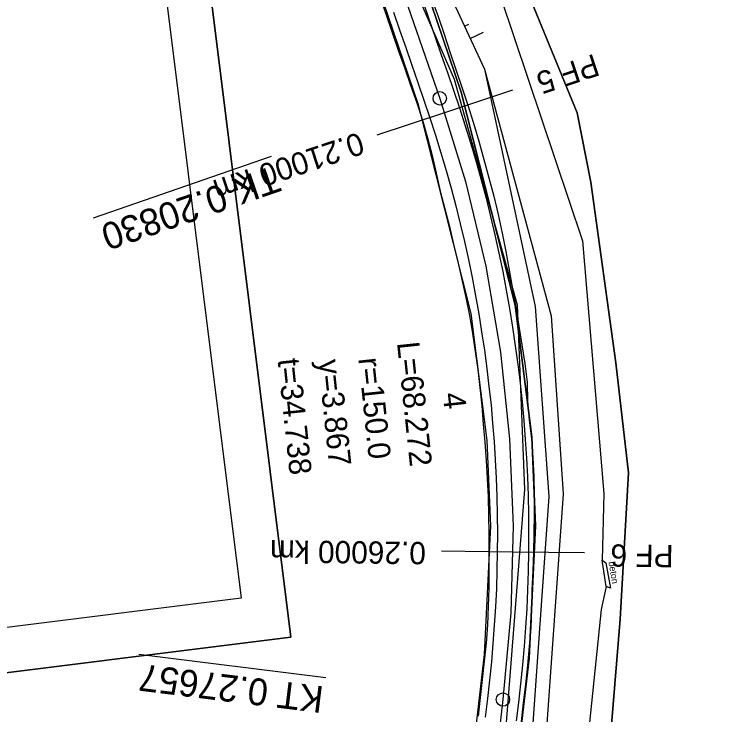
# Model space of a CAD drawing. Extents: x -555887 to -552101, y -1100251 to -1096546.
# Drawn here: x -553961.2 to -553879.9, y -1097845.2 to -1097766.8 of the extents above; entities that cross this region are included whole.
import ezdxf

# ---------------------------------------------------------------- set-up
doc = ezdxf.new("R2010")
doc.units = 0
for name, color, linetype in [('PARCELY_cesty', 7, 'Continuous'), ('PARCELY_VHO', 7, 'Continuous'), ('POLYGONY_SITUACE_PF', 7, 'Continuous'), ('POLYGONY_SITUACE_PF_POPISY', 7, 'Continuous'), ('POLYGONY_SITUACE_PO', 7, 'Continuous'), ('ROZHLED_ram_legenda_1', 7, 'Continuous'), ('ZSST', 7, 'Continuous'), ('zájem', 7, 'Continuous')]:
    doc.layers.add(name, color=color, linetype=linetype)

msp = doc.modelspace()

# ---------------------------------------------------------------- linework, layer by layer
for p, q in [((-553932.416, -1097782.755), (-553952.354, -1097789.637)), ((-553926.28, -1097841.093), (-553947.213, -1097838.51))]:
    msp.add_line(p, q)
at = {"layer": 'PARCELY_cesty'}
for points in [[(-553910.622, -1097956.19), (-553913.42, -1097924.46), (-553903.498, -1097838.889), (-553902.803, -1097824.091), (-553903.199, -1097814.131), (-553905.076, -1097799.369), (-553911.111, -1097775.519), (-553924.494, -1097736.179), (-553926.037, -1097728.701), (-553926.88, -1097721.034), (-553927.942, -1097698.335), (-553927.014, -1097685.697), (-553927.851, -1097681.722), (-553929.538, -1097678.1), (-553932.003, -1097674.954), (-553935.116, -1097672.449), (-553938.716, -1097670.715), (-553942.616, -1097669.842), (-553946.468, -1097669.874), (-554027.52, -1097678.879), (-554030.91, -1097678.33)], [(-553915.615, -1097956.495), (-553918.446, -1097924.391), (-553908.484, -1097838.483), (-553907.808, -1097824.073), (-553908.187, -1097814.546), (-553909.998, -1097800.301), (-553915.909, -1097776.94), (-553929.328, -1097737.494), (-553930.981, -1097729.481), (-553931.867, -1097721.425), (-553932.951, -1097698.268), (-553932.053, -1097686.035), (-553932.625, -1097683.313), (-553933.828, -1097680.732), (-553935.584, -1097678.49), (-553937.803, -1097676.705), (-553940.369, -1097675.469), (-553943.148, -1097674.846), (-553946.14, -1097674.871), (-554026.66, -1097685.902), (-554029.64, -1097687.62)]]:
    msp.add_lwpolyline(points, dxfattribs=at)
at = {"layer": 'PARCELY_VHO'}
for points in [[(-553895.01, -1097951.32), (-553903.94, -1097924.64), (-553898.75, -1097900.98), (-553893.31, -1097834.53), (-553892.36, -1097818.14), (-553893.78, -1097805.84), (-553896.6, -1097785.6), (-553898.1, -1097777.85), (-553916.6, -1097732.86), (-553916.42, -1097704.51), (-553918.4, -1097676.29), (-553917.8, -1097670.8), (-553913.5, -1097649.75), (-553920.52, -1097625.16)], [(-553927.41, -1097628.08), (-553920.29, -1097651.1), (-553924.15, -1097670.8), (-553927.014, -1097685.697), (-553927.942, -1097698.335), (-553926.88, -1097721.034), (-553926.037, -1097728.701), (-553924.494, -1097736.179), (-553911.111, -1097775.519), (-553905.076, -1097799.369), (-553903.199, -1097814.131), (-553902.803, -1097824.091), (-553903.498, -1097838.889), (-553913.42, -1097924.2), (-553904.91, -1097952.6), (-553904.09, -1097966.52), (-553910.368, -1097974.94), (-553913.828, -1098111.034), (-553912.715, -1098125.988), (-553910.789, -1098134.707), (-553870.98, -1098223.96)]]:
    msp.add_lwpolyline(points, dxfattribs=at)
at = {"layer": 'POLYGONY_SITUACE_PF'}
for p, q in [((-553905.372, -1097775.319), (-553912.964, -1097777.843)), ((-553912.964, -1097777.843), (-553920.555, -1097780.367)), ((-553905.313, -1097827.02), (-553913.312, -1097826.921)), ((-553897.313, -1097827.119), (-553905.313, -1097827.02))]:
    msp.add_line(p, q, dxfattribs=at)
at = {"layer": 'POLYGONY_SITUACE_PO'}
for p, q in [((-553925.367, -1097741.88), (-553913.51, -1097776.23)), ((-553920.205, -1097764.915), (-553919.528, -1097766.885)), ((-553915.379, -1097765.453), (-553914.699, -1097767.422)), ((-553915.379, -1097765.453), (-553914.699, -1097767.422)), ((-553914.388, -1097765.111), (-553913.694, -1097767.075)), ((-553918.687, -1097766.595), (-553918.008, -1097768.564)), ((-553918.687, -1097766.595), (-553918.008, -1097768.564)), ((-553919.528, -1097766.885), (-553918.851, -1097768.855)), ((-553914.699, -1097767.422), (-553914.019, -1097769.391)), ((-553914.699, -1097767.422), (-553914.019, -1097769.391)), ((-553913.694, -1097767.075), (-553913.036, -1097769.052)), ((-553918.851, -1097768.855), (-553918.181, -1097770.828)), ((-553918.008, -1097768.564), (-553917.328, -1097770.533)), ((-553918.008, -1097768.564), (-553917.328, -1097770.533)), ((-553913.036, -1097769.052), (-553912.373, -1097771.027)), ((-553914.019, -1097769.391), (-553913.34, -1097771.361)), ((-553914.019, -1097769.391), (-553913.34, -1097771.361)), ((-553917.328, -1097770.533), (-553916.648, -1097772.503)), ((-553917.328, -1097770.533), (-553916.648, -1097772.503)), ((-553918.181, -1097770.828), (-553917.479, -1097772.79)), ((-553913.34, -1097771.361), (-553912.66, -1097773.33)), ((-553913.34, -1097771.361), (-553912.66, -1097773.33)), ((-553912.373, -1097771.027), (-553911.708, -1097773.001)), ((-553917.479, -1097772.79), (-553916.79, -1097774.755)), ((-553916.648, -1097772.503), (-553915.968, -1097774.472)), ((-553916.648, -1097772.503), (-553915.968, -1097774.472)), ((-553911.708, -1097773.001), (-553911.042, -1097774.976)), ((-553912.66, -1097773.33), (-553911.98, -1097775.299)), ((-553912.66, -1097773.33), (-553911.98, -1097775.299)), ((-553916.79, -1097774.755), (-553916.081, -1097776.715)), ((-553915.968, -1097774.472), (-553915.289, -1097776.441)), ((-553915.968, -1097774.472), (-553915.289, -1097776.441)), ((-553911.98, -1097775.299), (-553911.303, -1097777.291)), ((-553911.98, -1097775.299), (-553911.303, -1097777.291)), ((-553911.042, -1097774.976), (-553910.376, -1097776.982)), ((-553913.51, -1097776.23), (-553910.63, -1097785.546)), ((-553916.081, -1097776.715), (-553915.465, -1097778.674)), ((-553915.289, -1097776.441), (-553914.624, -1097778.395)), ((-553915.289, -1097776.441), (-553914.624, -1097778.395)), ((-553910.376, -1097776.982), (-553909.743, -1097779.007)), ((-553911.303, -1097777.291), (-553910.658, -1097779.297)), ((-553911.303, -1097777.291), (-553910.658, -1097779.297)), ((-553915.465, -1097778.674), (-553914.896, -1097780.641)), ((-553914.624, -1097778.395), (-553913.994, -1097780.355)), ((-553914.624, -1097778.395), (-553913.994, -1097780.355)), ((-553910.658, -1097779.297), (-553910.031, -1097781.309)), ((-553910.658, -1097779.297), (-553910.031, -1097781.309)), ((-553909.743, -1097779.007), (-553909.143, -1097781.041)), ((-553913.994, -1097780.355), (-553913.382, -1097782.321)), ((-553913.994, -1097780.355), (-553913.382, -1097782.321)), ((-553914.896, -1097780.641), (-553914.365, -1097782.618)), ((-553909.143, -1097781.041), (-553908.573, -1097783.083)), ((-553910.031, -1097781.309), (-553909.433, -1097783.33)), ((-553910.031, -1097781.309), (-553909.433, -1097783.33)), ((-553914.365, -1097782.618), (-553913.903, -1097784.612)), ((-553913.382, -1097782.321), (-553912.798, -1097784.295)), ((-553913.382, -1097782.321), (-553912.798, -1097784.295)), ((-553909.433, -1097783.33), (-553908.873, -1097785.362)), ((-553909.433, -1097783.33), (-553908.873, -1097785.362)), ((-553908.573, -1097783.083), (-553908.029, -1097785.132)), ((-553912.798, -1097784.295), (-553912.251, -1097786.28)), ((-553912.798, -1097784.295), (-553912.251, -1097786.28)), ((-553913.903, -1097784.612), (-553913.454, -1097786.607)), ((-553908.029, -1097785.132), (-553907.456, -1097787.174)), ((-553910.63, -1097785.546), (-553908.361, -1097795.03)), ((-553908.873, -1097785.362), (-553908.331, -1097787.399)), ((-553908.873, -1097785.362), (-553908.331, -1097787.399)), ((-553913.454, -1097786.607), (-553912.947, -1097788.585)), ((-553912.251, -1097786.28), (-553911.721, -1097788.27)), ((-553912.251, -1097786.28), (-553911.721, -1097788.27)), ((-553908.331, -1097787.399), (-553907.821, -1097789.444)), ((-553908.331, -1097787.399), (-553907.821, -1097789.444)), ((-553907.456, -1097787.174), (-553906.956, -1097789.234)), ((-553912.947, -1097788.585), (-553912.44, -1097790.563)), ((-553911.721, -1097788.27), (-553911.222, -1097790.268)), ((-553911.721, -1097788.27), (-553911.222, -1097790.268)), ((-553906.956, -1097789.234), (-553906.515, -1097791.308)), ((-553907.821, -1097789.444), (-553907.339, -1097791.495)), ((-553907.821, -1097789.444), (-553907.339, -1097791.495)), ((-553912.44, -1097790.563), (-553911.96, -1097792.547)), ((-553911.222, -1097790.268), (-553910.752, -1097792.272)), ((-553911.222, -1097790.268), (-553910.752, -1097792.272)), ((-553907.339, -1097791.495), (-553906.878, -1097793.552)), ((-553907.339, -1097791.495), (-553906.878, -1097793.552)), ((-553906.515, -1097791.308), (-553906.097, -1097793.385)), ((-553911.96, -1097792.547), (-553911.486, -1097794.533)), ((-553910.752, -1097792.272), (-553910.301, -1097794.281)), ((-553910.752, -1097792.272), (-553910.301, -1097794.281)), ((-553906.097, -1097793.385), (-553905.726, -1097795.472)), ((-553910.301, -1097794.281), (-553909.897, -1097796.3)), ((-553910.301, -1097794.281), (-553909.897, -1097796.3)), ((-553906.878, -1097793.552), (-553906.464, -1097795.618)), ((-553906.878, -1097793.552), (-553906.464, -1097795.618)), ((-553911.486, -1097794.533), (-553911.038, -1097796.527)), ((-553908.361, -1097795.03), (-553906.713, -1097804.641)), ((-553906.464, -1097795.618), (-553906.067, -1097797.688)), ((-553906.464, -1097795.618), (-553906.067, -1097797.688)), ((-553905.726, -1097795.472), (-553905.347, -1097797.556)), ((-553911.038, -1097796.527), (-553910.596, -1097798.522)), ((-553909.897, -1097796.3), (-553909.509, -1097798.322)), ((-553909.897, -1097796.3), (-553909.509, -1097798.322)), ((-553909.509, -1097798.322), (-553909.144, -1097800.349)), ((-553909.509, -1097798.322), (-553909.144, -1097800.349)), ((-553906.067, -1097797.688), (-553905.694, -1097799.763)), ((-553906.067, -1097797.688), (-553905.694, -1097799.763)), ((-553905.347, -1097797.556), (-553904.989, -1097799.643)), ((-553910.596, -1097798.522), (-553910.191, -1097800.526)), ((-553905.694, -1097799.763), (-553905.36, -1097801.844)), ((-553905.694, -1097799.763), (-553905.36, -1097801.844)), ((-553904.989, -1097799.643), (-553904.64, -1097801.732)), ((-553910.191, -1097800.526), (-553909.844, -1097802.541)), ((-553909.144, -1097800.349), (-553908.818, -1097802.382)), ((-553909.144, -1097800.349), (-553908.818, -1097802.382)), ((-553908.818, -1097802.382), (-553908.511, -1097804.418)), ((-553908.818, -1097802.382), (-553908.511, -1097804.418)), ((-553905.36, -1097801.844), (-553905.046, -1097803.928)), ((-553905.36, -1097801.844), (-553905.046, -1097803.928)), ((-553904.64, -1097801.732), (-553904.306, -1097803.823)), ((-553909.844, -1097802.541), (-553909.542, -1097804.563)), ((-553905.046, -1097803.928), (-553904.771, -1097806.017)), ((-553905.046, -1097803.928), (-553904.771, -1097806.017)), ((-553904.306, -1097803.823), (-553903.973, -1097805.916)), ((-553909.542, -1097804.563), (-553909.254, -1097806.588)), ((-553908.511, -1097804.418), (-553908.243, -1097806.459)), ((-553908.511, -1097804.418), (-553908.243, -1097806.459)), ((-553906.713, -1097804.641), (-553905.693, -1097814.339)), ((-553908.243, -1097806.459), (-553907.998, -1097808.503)), ((-553908.243, -1097806.459), (-553907.998, -1097808.503)), ((-553904.771, -1097806.017), (-553904.521, -1097808.11)), ((-553904.771, -1097806.017), (-553904.521, -1097808.11)), ((-553903.973, -1097805.916), (-553903.716, -1097808.019)), ((-553909.254, -1097806.588), (-553909.03, -1097808.62)), ((-553903.716, -1097808.019), (-553903.679, -1097810.144)), ((-553909.03, -1097808.62), (-553908.807, -1097810.652)), ((-553907.998, -1097808.503), (-553907.77, -1097810.55)), ((-553907.998, -1097808.503), (-553907.77, -1097810.55)), ((-553904.521, -1097808.11), (-553904.287, -1097810.204)), ((-553904.521, -1097808.11), (-553904.287, -1097810.204)), ((-553904.287, -1097810.204), (-553904.102, -1097812.304)), ((-553904.287, -1097810.204), (-553904.102, -1097812.304)), ((-553903.679, -1097810.144), (-553903.495, -1097812.252)), ((-553908.807, -1097810.652), (-553908.651, -1097812.691)), ((-553907.77, -1097810.55), (-553907.589, -1097812.601)), ((-553907.77, -1097810.55), (-553907.589, -1097812.601)), ((-553908.651, -1097812.691), (-553908.474, -1097814.728)), ((-553907.589, -1097812.601), (-553907.429, -1097814.653)), ((-553907.589, -1097812.601), (-553907.429, -1097814.653)), ((-553904.102, -1097812.304), (-553903.937, -1097814.405)), ((-553904.102, -1097812.304), (-553903.937, -1097814.405)), ((-553903.495, -1097812.252), (-553903.229, -1097814.355)), ((-553905.693, -1097814.339), (-553905.305, -1097824.082)), ((-553903.937, -1097814.405), (-553903.802, -1097816.508)), ((-553903.937, -1097814.405), (-553903.802, -1097816.508)), ((-553903.229, -1097814.355), (-553903.094, -1097816.468)), ((-553908.474, -1097814.728), (-553908.317, -1097816.767)), ((-553907.429, -1097814.653), (-553907.297, -1097816.708)), ((-553907.429, -1097814.653), (-553907.297, -1097816.708)), ((-553908.317, -1097816.767), (-553908.199, -1097818.808)), ((-553907.297, -1097816.708), (-553907.197, -1097818.765)), ((-553907.297, -1097816.708), (-553907.197, -1097818.765)), ((-553903.802, -1097816.508), (-553903.7, -1097818.613)), ((-553903.802, -1097816.508), (-553903.7, -1097818.613)), ((-553903.094, -1097816.468), (-553902.982, -1097818.582)), ((-553903.7, -1097818.613), (-553903.616, -1097820.719)), ((-553903.7, -1097818.613), (-553903.616, -1097820.719)), ((-553902.982, -1097818.582), (-553902.944, -1097820.7)), ((-553908.199, -1097818.808), (-553908.1, -1097820.851)), ((-553907.197, -1097818.765), (-553907.115, -1097820.822)), ((-553907.197, -1097818.765), (-553907.115, -1097820.822)), ((-553908.1, -1097820.851), (-553908.044, -1097822.896)), ((-553907.115, -1097820.822), (-553907.071, -1097822.881)), ((-553907.115, -1097820.822), (-553907.071, -1097822.881)), ((-553903.616, -1097820.719), (-553903.572, -1097822.826)), ((-553903.616, -1097820.719), (-553903.572, -1097822.826)), ((-553902.944, -1097820.7), (-553902.946, -1097822.817)), ((-553908.044, -1097822.896), (-553908.012, -1097824.941)), ((-553907.071, -1097822.881), (-553907.057, -1097824.939)), ((-553907.071, -1097822.881), (-553907.057, -1097824.939)), ((-553903.572, -1097822.826), (-553903.557, -1097824.934)), ((-553903.572, -1097822.826), (-553903.557, -1097824.934)), ((-553902.946, -1097822.817), (-553902.977, -1097824.933)), ((-553905.305, -1097824.082), (-553905.551, -1097833.83)), ((-553908.012, -1097824.941), (-553907.998, -1097826.987)), ((-553907.057, -1097824.939), (-553907.063, -1097826.998)), ((-553907.057, -1097824.939), (-553907.063, -1097826.998)), ((-553903.557, -1097824.934), (-553903.563, -1097827.042)), ((-553903.557, -1097824.934), (-553903.563, -1097827.042)), ((-553902.977, -1097824.933), (-553903.022, -1097827.048)), ((-553907.998, -1097826.987), (-553908.007, -1097829.033)), ((-553907.063, -1097826.998), (-553907.108, -1097829.057)), ((-553907.063, -1097826.998), (-553907.108, -1097829.057)), ((-553903.563, -1097827.042), (-553903.609, -1097829.149)), ((-553903.563, -1097827.042), (-553903.609, -1097829.149)), ((-553903.022, -1097827.048), (-553903.102, -1097829.162)), ((-553908.007, -1097829.033), (-553908.008, -1097831.081)), ((-553907.108, -1097829.057), (-553907.173, -1097831.115)), ((-553907.108, -1097829.057), (-553907.173, -1097831.115)), ((-553903.609, -1097829.149), (-553903.676, -1097831.255)), ((-553903.609, -1097829.149), (-553903.676, -1097831.255)), ((-553903.102, -1097829.162), (-553903.202, -1097831.274)), ((-553908.008, -1097831.081), (-553908.075, -1097833.128)), ((-553907.173, -1097831.115), (-553907.267, -1097833.172)), ((-553907.173, -1097831.115), (-553907.267, -1097833.172)), ((-553903.676, -1097831.255), (-553903.772, -1097833.361)), ((-553903.676, -1097831.255), (-553903.772, -1097833.361)), ((-553903.202, -1097831.274), (-553903.247, -1097833.389)), ((-553908.075, -1097833.128), (-553908.158, -1097835.175)), ((-553907.267, -1097833.172), (-553907.4, -1097835.226)), ((-553907.267, -1097833.172), (-553907.4, -1097835.226)), ((-553905.551, -1097833.83), (-553906.431, -1097843.542)), ((-553903.772, -1097833.361), (-553903.908, -1097835.464)), ((-553903.772, -1097833.361), (-553903.908, -1097835.464)), ((-553903.247, -1097833.389), (-553903.313, -1097835.504)), ((-553908.158, -1097835.175), (-553908.33, -1097837.216)), ((-553907.4, -1097835.226), (-553907.55, -1097837.28)), ((-553907.4, -1097835.226), (-553907.55, -1097837.28)), ((-553903.908, -1097835.464), (-553904.062, -1097837.566)), ((-553903.908, -1097835.464), (-553904.062, -1097837.566)), ((-553903.313, -1097835.504), (-553903.478, -1097837.613)), ((-553908.33, -1097837.216), (-553908.546, -1097839.253)), ((-553907.55, -1097837.28), (-553907.731, -1097839.331)), ((-553907.55, -1097837.28), (-553907.731, -1097839.331)), ((-553904.062, -1097837.566), (-553904.247, -1097839.665)), ((-553904.062, -1097837.566), (-553904.247, -1097839.665)), ((-553903.478, -1097837.613), (-553903.675, -1097839.72)), ((-553908.546, -1097839.253), (-553908.775, -1097841.287)), ((-553907.731, -1097839.331), (-553907.945, -1097841.379)), ((-553907.731, -1097839.331), (-553907.945, -1097841.379)), ((-553904.247, -1097839.665), (-553904.466, -1097841.761)), ((-553904.247, -1097839.665), (-553904.466, -1097841.761)), ((-553903.675, -1097839.72), (-553903.902, -1097841.823)), ((-553908.775, -1097841.287), (-553908.981, -1097843.326)), ((-553907.945, -1097841.379), (-553908.179, -1097843.425)), ((-553907.945, -1097841.379), (-553908.179, -1097843.425)), ((-553904.466, -1097841.761), (-553904.706, -1097843.854)), ((-553904.466, -1097841.761), (-553904.706, -1097843.854)), ((-553903.902, -1097841.823), (-553904.151, -1097843.923)), ((-553906.431, -1097843.542), (-553915.579, -1097917.677)), ((-553908.981, -1097843.326), (-553909.207, -1097845.398)), ((-553908.179, -1097843.425), (-553908.435, -1097845.493)), ((-553908.179, -1097843.425), (-553908.435, -1097845.493)), ((-553904.706, -1097843.854), (-553904.961, -1097845.922)), ((-553904.706, -1097843.854), (-553904.961, -1097845.922)), ((-553904.151, -1097843.923), (-553904.405, -1097845.99))]:
    msp.add_line(p, q, dxfattribs=at)
for centre in [(-553913.51, -1097776.23), (-553906.431, -1097843.542)]:
    msp.add_circle(centre, 0.75, dxfattribs=at)
at = {"layer": 'ROZHLED_ram_legenda_1'}
msp.add_lwpolyline([(-553930.196, -1097836.542), (-554138.575, -1097862.587), (-554175.41, -1097567.88), (-553967.031, -1097541.835)], close=True, dxfattribs=at)
msp.add_lwpolyline([(-553930.196, -1097836.542), (-554138.575, -1097862.587), (-554175.41, -1097567.88), (-553967.031, -1097541.835)], close=True, dxfattribs=at)
for points in [[(-553967.031, -1097541.835), (-554175.41, -1097567.88), (-554138.575, -1097862.587), (-553930.196, -1097836.542), (-553967.031, -1097541.835)], [(-554134.234, -1097857.005), (-554169.828, -1097572.221), (-553971.373, -1097547.416), (-553935.778, -1097832.201), (-554134.234, -1097857.005)], [(-554134.234, -1097857.005), (-554169.828, -1097572.221), (-553971.373, -1097547.416), (-553935.778, -1097832.201), (-554134.234, -1097857.005)]]:
    msp.add_lwpolyline(points, dxfattribs=at)
at = {"layer": 'ZSST'}
for p, q in [((-553910.739, -1097768.162), (-553910.243, -1097767.931)), ((-553910.107, -1097769.522), (-553908.617, -1097768.83))]:
    msp.add_line(p, q, dxfattribs=at)
for points in [[(-553924.66, -1097729.04), (-553921.53, -1097741.78), (-553916.02, -1097756.79), (-553908.51, -1097772.96), (-553902.81, -1097799.53), (-553901.3, -1097820.82), (-553903.22, -1097848.29), (-553905.59, -1097881.04), (-553905.22, -1097893.91), (-553907.85, -1097907.67), (-553911.16, -1097917.96), (-553910.53, -1097929.5), (-553905.13, -1097944.97), (-553902.46, -1097958.37), (-553903.33, -1097964.72)], [(-553918.94, -1097738.08), (-553906.7, -1097764.83), (-553897.52, -1097792.18), (-553895.14, -1097820.47), (-553895.3, -1097827.93)], [(-553920.88, -1097754.01), (-553919.13, -1097757.44), (-553911.89, -1097774.1), (-553904.85, -1097799.34), (-553904.03, -1097820.03), (-553906.32, -1097849.41), (-553909.08, -1097888.54)], [(-553908.51, -1097772.96), (-553901.02, -1097800.59), (-553899.7, -1097820.5), (-553901.7, -1097848.88), (-553905.59, -1097881.04)], [(-553894.87, -1097830.87), (-553895.44, -1097833.46), (-553897.92, -1097857.69), (-553897.54, -1097871.22), (-553900.41, -1097888.86), (-553902.99, -1097909.34), (-553907.18, -1097920.45), (-553905.9, -1097929.65), (-553896.22, -1097956.42), (-553897.58, -1097967.85)]]:
    msp.add_lwpolyline(points, dxfattribs=at)
msp.add_lwpolyline([(-553895.3, -1097827.93), (-553894.92, -1097828.23), (-553894.38, -1097831.07), (-553894.87, -1097830.87)], close=True, dxfattribs=at)
at = {"layer": 'zájem'}
for points in [[(-553873.44, -1097756.54), (-553881.15, -1097737.32), (-553890.36, -1097670.23), (-553917.8, -1097670.8), (-553918.4, -1097676.29), (-553916.42, -1097704.51), (-553916.6, -1097732.86), (-553898.1, -1097777.85), (-553896.6, -1097785.6), (-553893.78, -1097805.84), (-553892.36, -1097818.14), (-553893.31, -1097834.53), (-553898.75, -1097900.98), (-553903.94, -1097924.64), (-553895.01, -1097951.32)], [(-553895.01, -1097951.32), (-553903.94, -1097924.64), (-553898.75, -1097900.98), (-553893.31, -1097834.53), (-553892.36, -1097818.14), (-553893.78, -1097805.84), (-553896.6, -1097785.6), (-553898.1, -1097777.85), (-553916.6, -1097732.86), (-553916.42, -1097704.51), (-553918.4, -1097676.29), (-553917.8, -1097670.8), (-553890.36, -1097670.23), (-553881.15, -1097737.32), (-553873.44, -1097756.54)]]:
    msp.add_lwpolyline(points, dxfattribs=at)

# ---------------------------------------------------------------- texts
for s, height, rotation, p in [('TK 0.20830', 3, 199.04308, (-553932.09, -1097783.7)), ('L=68.272', 2.5, 276.00417, (-553918.307, -1097803.589)), ('t=34.738', 2.5, 276.00417, (-553931.685, -1097805.46)), ('y=3.867', 2.5, 276.00417, (-553927.147, -1097805.582)), ('r=150.0', 2.5, 276.00417, (-553922.646, -1097805.36)), ('4', 2.5, 276.00417, (-553913.184, -1097809.276)), ('KT 0.27657', 3, 172.96527, (-553926.402, -1097842.085))]:
    msp.add_text(s, height=height, rotation=rotation).set_placement(p)
at = {"layer": 'POLYGONY_SITUACE_PF_POPISY'}
for s, rotation, p in [('PF 5', 198.39251, (-553896.199, -1097771.214)), ('0.21000 km', 198.39251, (-553922.534, -1097779.971)), ('0.26000 km', 179.29391, (-553915.053, -1097825.9)), ('PF 6', 179.29391, (-553887.302, -1097826.242))]:
    msp.add_text(s, height=2.5, rotation=rotation, dxfattribs=at).set_placement(p)
at = {"layer": 'ZSST'}
msp.add_text('beton', height=0.75, rotation=279.6034, dxfattribs=at).set_placement((-553894.615, -1097828.144))

doc.saveas('drawing.dxf')
